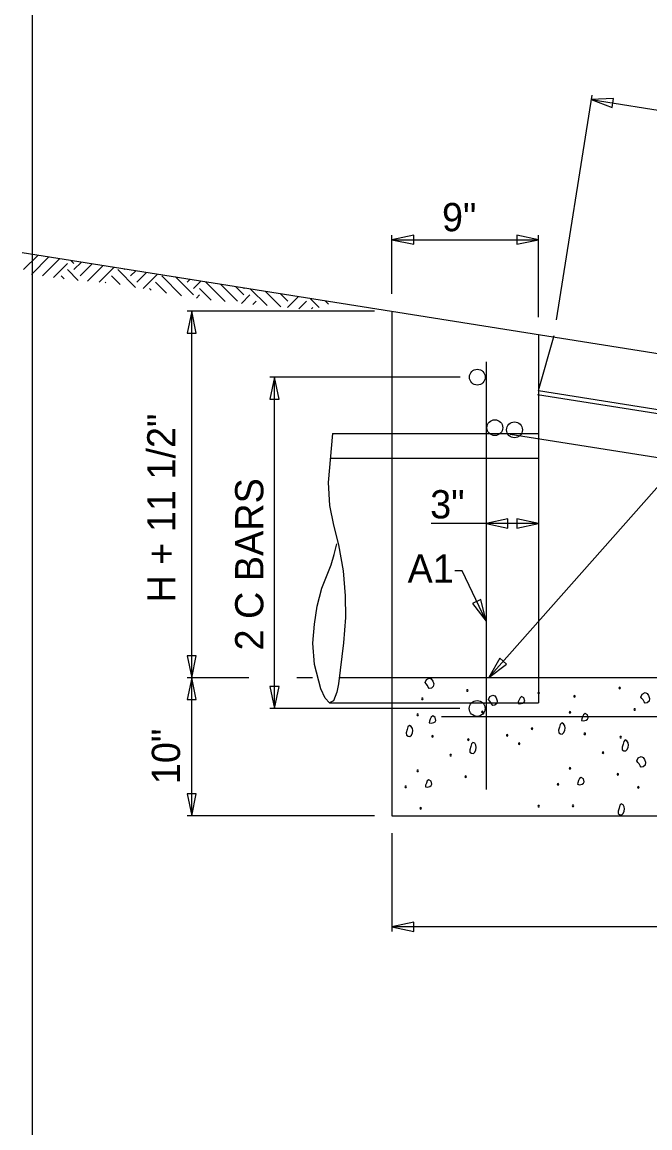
# Model space of a CAD drawing. Extents: x -439.2 to -407.9, y -458.1 to -436.2.
# Drawn here: x -439.16 to -435.83, y -452.18 to -446.32 of the extents above; entities that cross this region are included whole.
import ezdxf

# ---------------------------------------------------------------- set-up
doc = ezdxf.new("R2010")
doc.units = 0
for name, color, linetype in [('Bridge-Named Boundary', 7, 'Continuous'), ('Level 4', 7, 'Continuous'), ('Level 45', 7, 'Continuous')]:
    doc.layers.add(name, color=color, linetype=linetype)

msp = doc.modelspace()

# ---------------------------------------------------------------- linework, layer by layer
at = {"layer": 'Bridge-Named Boundary'}
msp.add_lwpolyline([(-439.109, -458.0508), (-407.859, -458.0508), (-407.859, -437.6758), (-439.109, -437.6758)], close=True, dxfattribs=at)
at = {"layer": 'Level 4'}
for p, q in [((-436.3245, -447.8963), (-436.1357, -446.7046)), ((-436.1395, -446.7284), (-430.9827, -447.5452)), ((-437.1989, -447.759), (-437.1989, -447.4476)), ((-436.4192, -447.8825), (-436.4192, -447.4476)), ((-437.1989, -447.4717), (-436.4192, -447.4717)), ((-439.1627, -447.54), (-425.6904, -449.6734)), ((-439.1551, -447.6305), (-439.0782, -447.5535)), ((-439.1136, -447.6558), (-439.0205, -447.5627)), ((-439.0549, -447.664), (-438.9628, -447.5718)), ((-438.8879, -447.5971), (-438.9038, -447.5812)), ((-438.9963, -447.6721), (-438.9213, -447.5971)), ((-438.8645, -447.6873), (-438.9213, -447.6305)), ((-438.8879, -447.6305), (-438.8475, -447.5901)), ((-438.8544, -447.6639), (-438.7898, -447.5993)), ((-438.8153, -447.6916), (-438.7321, -447.6084)), ((-438.7538, -447.697), (-438.6745, -447.6176)), ((-438.5601, -447.7244), (-438.654, -447.6305)), ((-438.6206, -447.6305), (-438.6168, -447.6267)), ((-438.5872, -447.6639), (-438.5591, -447.6359)), ((-438.9386, -447.68), (-438.9547, -447.6639)), ((-438.7177, -447.7005), (-438.7208, -447.6973)), ((-438.6419, -447.7095), (-438.6874, -447.6639)), ((-438.5537, -447.6973), (-438.5014, -447.645)), ((-438.5203, -447.7308), (-438.4438, -447.6542)), ((-438.3956, -447.7553), (-438.4535, -447.6973)), ((-438.3153, -447.7688), (-438.4201, -447.6639)), ((-438.2531, -447.7642), (-438.3478, -447.6694)), ((-438.2865, -447.6973), (-438.2708, -447.6816)), ((-438.2531, -447.7308), (-438.2131, -447.6908)), ((-438.0835, -447.8), (-438.1862, -447.6973)), ((-438.4779, -447.7398), (-438.4869, -447.7308)), ((-438.1583, -447.7921), (-438.2196, -447.7308)), ((-438.0192, -447.7976), (-438.1095, -447.7072)), ((-437.9858, -447.7642), (-438.0301, -447.7198)), ((-437.9858, -447.7308), (-437.9824, -447.7274)), ((-437.8619, -447.8212), (-437.9507, -447.7324)), ((-437.789, -447.8273), (-437.8713, -447.745)), ((-438.2372, -447.7818), (-438.2196, -447.7642)), ((-437.9974, -447.8092), (-437.9524, -447.7642)), ((-437.9364, -447.815), (-437.9189, -447.7976)), ((-437.7519, -447.7976), (-437.7918, -447.7576)), ((-437.7526, -447.8317), (-437.694, -447.7731)), ((-437.6931, -447.839), (-437.6517, -447.7976)), ((-437.5847, -447.8311), (-437.633, -447.7828)), ((-437.5352, -447.8138), (-437.5536, -447.7954)), ((-437.2907, -447.8509), (-438.2861, -447.8509)), ((-438.262, -450.5286), (-438.262, -447.8509)), ((-437.6256, -447.8384), (-437.6182, -447.831)), ((-437.1984, -447.8506), (-437.1984, -450.5281)), ((-436.6846, -449.7952), (-434.9984, -447.8922)), ((-436.4193, -447.9745), (-436.4193, -449.9295)), ((-436.4193, -448.2716), (-436.3374, -447.9797)), ((-436.6986, -448.1194), (-436.6986, -450.3884)), ((-436.8369, -448.2012), (-437.8461, -448.2012)), ((-437.822, -449.9585), (-437.822, -448.2012)), ((-436.4193, -448.2716), (-431.2564, -449.0896)), ((-436.4245, -448.2926), (-431.261, -449.11)), ((-437.5136, -448.4995), (-436.4193, -448.4995)), ((-436.5705, -448.5037), (-430.4973, -449.4655)), ((-436.4193, -448.6328), (-437.5256, -448.6328)), ((-436.4192, -448.9772), (-436.9909, -448.9772)), ((-436.825, -449.2287), (-436.8649, -449.2287)), ((-436.6985, -449.4959), (-436.825, -449.2287)), ((-437.9591, -449.7955), (-438.2861, -449.7955)), ((-437.6207, -449.7955), (-437.7027, -449.7955)), ((-437.4775, -449.7952), (-436.4193, -449.7952)), ((-436.4193, -449.7952), (-425.6904, -449.7952)), ((-436.8377, -449.9585), (-437.8461, -449.9585)), ((-437.5304, -449.9295), (-436.4193, -449.9295)), ((-436.9348, -450.001), (-431.0317, -450.001)), ((-437.2907, -450.5286), (-438.2861, -450.5286)), ((-437.1984, -450.5281), (-425.6904, -450.5281)), ((-437.1989, -450.6204), (-437.1989, -451.1415)), ((-425.6902, -451.1174), (-437.1989, -451.1174))]:
    msp.add_line(p, q, dxfattribs=at)
for points in [[(-436.021, -446.7228), (-436.1395, -446.7284), (-436.0285, -446.7704)], [(-437.0827, -447.4476), (-437.1989, -447.4717), (-437.0827, -447.4958)], [(-436.5354, -447.4958), (-436.4192, -447.4717), (-436.5354, -447.4476)], [(-438.2379, -447.967), (-438.262, -447.8509), (-438.2861, -447.967)], [(-437.7979, -448.3174), (-437.822, -448.2012), (-437.8461, -448.3174)], [(-436.5823, -448.9531), (-436.6985, -448.9772), (-436.5823, -449.0013)], [(-436.5354, -449.0013), (-436.4192, -448.9772), (-436.5354, -448.9531)], [(-436.77, -449.4012), (-436.6985, -449.4959), (-436.7264, -449.3806)], [(-438.2861, -449.6793), (-438.262, -449.7955), (-438.2379, -449.6793)], [(-436.6256, -449.6922), (-436.6846, -449.7952), (-436.5895, -449.7242)], [(-438.2379, -449.9116), (-438.262, -449.7955), (-438.2861, -449.9116)], [(-437.0219, -449.8208), (-437.0153, -449.8051), (-436.9998, -449.7975), (-436.9895, -449.8023), (-436.9816, -449.813), (-436.9759, -449.8283), (-436.979, -449.8429), (-436.9891, -449.8517), (-436.9998, -449.8533), (-437.0053, -449.8462), (-437.0102, -449.8364), (-437.0172, -449.8288), (-437.0219, -449.8208)], [(-437.8461, -449.8423), (-437.822, -449.9585), (-437.7979, -449.8423)], [(-436.6848, -449.9108), (-436.6783, -449.8951), (-436.6628, -449.8875), (-436.6525, -449.8923), (-436.6446, -449.9031), (-436.6389, -449.9183), (-436.642, -449.9329), (-436.652, -449.9417), (-436.6628, -449.9433), (-436.6682, -449.9362), (-436.6732, -449.9264), (-436.6802, -449.9188), (-436.6848, -449.9108)], [(-436.5098, -449.8957), (-436.5176, -449.9016), (-436.5228, -449.9126), (-436.5275, -449.9238), (-436.528, -449.932), (-436.5185, -449.9344), (-436.5046, -449.9307), (-436.4968, -449.926), (-436.4929, -449.9191), (-436.4972, -449.9031), (-436.5098, -449.8957)], [(-435.8759, -449.8979), (-435.8694, -449.8822), (-435.8539, -449.8746), (-435.8436, -449.8794), (-435.8357, -449.8902), (-435.83, -449.9054), (-435.8331, -449.92), (-435.8431, -449.9288), (-435.8539, -449.9304), (-435.8593, -449.9233), (-435.8642, -449.9135), (-435.8713, -449.9059), (-435.8759, -449.8979)], [(-436.1727, -449.9857), (-436.1805, -449.9916), (-436.1857, -450.0026), (-436.1905, -450.0138), (-436.1909, -450.022), (-436.1814, -450.0244), (-436.1676, -450.0207), (-436.1598, -450.016), (-436.1559, -450.0091), (-436.1601, -449.9931), (-436.1727, -449.9857)], [(-436.9817, -449.9986), (-436.9894, -450.0045), (-436.9946, -450.0155), (-436.9994, -450.0267), (-436.9998, -450.0349), (-436.9903, -450.0373), (-436.9765, -450.0337), (-436.9687, -450.0289), (-436.9648, -450.022), (-436.969, -450.006), (-436.9817, -449.9986)], [(-436.2966, -450.0358), (-436.3045, -450.0432), (-436.3083, -450.0579), (-436.3136, -450.0746), (-436.3121, -450.0877), (-436.304, -450.0933), (-436.294, -450.0942), (-436.2855, -450.0868), (-436.281, -450.0747), (-436.2792, -450.063), (-436.281, -450.0514), (-436.287, -450.0406), (-436.2966, -450.0358)], [(-437.1055, -450.0487), (-437.1134, -450.0561), (-437.1172, -450.0708), (-437.1225, -450.0876), (-437.1211, -450.1006), (-437.1129, -450.1062), (-437.1029, -450.1071), (-437.0945, -450.0997), (-437.0899, -450.0876), (-437.0881, -450.0759), (-437.0899, -450.0643), (-437.0959, -450.0535), (-437.1055, -450.0487)], [(-436.7684, -450.1387), (-436.7764, -450.1461), (-436.7801, -450.1608), (-436.7854, -450.1776), (-436.784, -450.1906), (-436.7758, -450.1962), (-436.7659, -450.1971), (-436.7574, -450.1897), (-436.7529, -450.1777), (-436.751, -450.1659), (-436.7529, -450.1543), (-436.7589, -450.1435), (-436.7684, -450.1387)], [(-435.9595, -450.1258), (-435.9675, -450.1332), (-435.9712, -450.1479), (-435.9765, -450.1646), (-435.9751, -450.1777), (-435.9669, -450.1833), (-435.9569, -450.1842), (-435.9485, -450.1768), (-435.944, -450.1647), (-435.9421, -450.153), (-435.944, -450.1414), (-435.95, -450.1306), (-435.9595, -450.1258)], [(-435.897, -450.2369), (-435.8904, -450.2212), (-435.8749, -450.2135), (-435.8646, -450.2184), (-435.8568, -450.2291), (-435.851, -450.2444), (-435.8542, -450.259), (-435.8642, -450.2678), (-435.8749, -450.2693), (-435.8804, -450.2623), (-435.8853, -450.2525), (-435.8923, -450.2449), (-435.897, -450.2369)], [(-437.0027, -450.3376), (-437.0105, -450.3435), (-437.0157, -450.3544), (-437.0205, -450.3657), (-437.0209, -450.3739), (-437.0114, -450.3762), (-436.9975, -450.3726), (-436.9898, -450.3678), (-436.9858, -450.3609), (-436.9901, -450.345), (-437.0027, -450.3376)], [(-436.1938, -450.3246), (-436.2016, -450.3305), (-436.2068, -450.3415), (-436.2115, -450.3528), (-436.212, -450.361), (-436.2025, -450.3633), (-436.1886, -450.3597), (-436.1808, -450.3549), (-436.1769, -450.348), (-436.1812, -450.3321), (-436.1938, -450.3246)], [(-438.2861, -450.4124), (-438.262, -450.5286), (-438.2379, -450.4124)], [(-435.9806, -450.4648), (-435.9885, -450.4722), (-435.9923, -450.4868), (-435.9976, -450.5036), (-435.9962, -450.5167), (-435.988, -450.5223), (-435.978, -450.5232), (-435.9696, -450.5158), (-435.965, -450.5037), (-435.9632, -450.492), (-435.965, -450.4803), (-435.971, -450.4695), (-435.9806, -450.4648)], [(-437.0827, -451.0933), (-437.1989, -451.1174), (-437.0827, -451.1415)]]:
    msp.add_lwpolyline(points, close=True, dxfattribs=at)
msp.add_lwpolyline([(-437.5136, -448.4995), (-437.537, -448.7596), (-437.5304, -448.8815), (-437.5083, -448.9856), (-437.4816, -449.0902), (-437.4573, -449.2278), (-437.446, -449.3611), (-437.4459, -449.4755), (-437.4549, -449.6098), (-437.4814, -449.8273), (-437.4912, -449.8718), (-437.5089, -449.918), (-437.5304, -449.9295), (-437.5526, -449.9049), (-437.5752, -449.8553), (-437.6103, -449.7253), (-437.6192, -449.613), (-437.6103, -449.5121), (-437.5953, -449.4166), (-437.5704, -449.3212), (-437.5461, -449.2588), (-437.5215, -449.1968), (-437.5044, -449.1418), (-437.4905, -449.0858)], dxfattribs=at)
for centre in [(-436.745, -448.2012), (-436.6519, -448.4689), (-436.5472, -448.4805), (-436.7458, -449.9585)]:
    msp.add_circle(centre, 0.042, dxfattribs=at)
for centre, start, end in [((-436.7976, -449.8632), 0, 180), ((-436.7976, -449.8632), 180, 0), ((-435.9887, -449.8503), 0, 180), ((-435.9887, -449.8503), 180, 0), ((-437.0375, -449.9077), 0, 180), ((-437.0375, -449.9077), 180, 0), ((-436.4193, -449.8772), 0, 180), ((-436.4193, -449.8772), 180, 0), ((-436.2286, -449.8948), 0, 180), ((-436.2286, -449.8948), 180, 0), ((-436.7186, -449.9772), 0, 180), ((-436.7186, -449.9772), 180, 0), ((-436.2531, -449.9793), 0, 180), ((-436.2531, -449.9793), 180, 0), ((-435.9097, -449.9643), 0, 180), ((-435.9097, -449.9643), 180, 0), ((-437.0621, -449.9922), 0, 180), ((-437.0621, -449.9922), 180, 0), ((-436.9831, -450.1062), 0, 180), ((-436.5863, -450.1018), 0, 180), ((-436.5863, -450.1018), 180, 0), ((-436.4543, -450.0657), 0, 180), ((-436.4543, -450.0657), 180, 0), ((-436.1742, -450.0933), 0, 180), ((-436.1742, -450.0933), 180, 0), ((-436.9831, -450.1062), 180, 0), ((-436.7923, -450.1237), 0, 180), ((-436.7923, -450.1237), 180, 0), ((-436.5225, -450.1454), 0, 180), ((-436.5225, -450.1454), 180, 0), ((-435.9834, -450.1108), 0, 180), ((-435.9834, -450.1108), 180, 0), ((-436.8863, -450.2067), 0, 180), ((-436.8863, -450.2067), 180, 0), ((-436.0774, -450.1937), 0, 180), ((-436.0774, -450.1937), 180, 0), ((-436.2527, -450.2769), 0, 180), ((-436.2527, -450.2769), 180, 0), ((-437.0617, -450.2898), 0, 180), ((-437.0617, -450.2898), 180, 0), ((-436.8073, -450.3207), 0, 180), ((-436.8073, -450.3207), 180, 0), ((-435.9984, -450.3078), 0, 180), ((-435.9984, -450.3078), 180, 0), ((-437.125, -450.3744), 0, 180), ((-437.125, -450.3744), 180, 0), ((-436.316, -450.3615), 0, 180), ((-436.316, -450.3615), 180, 0), ((-435.8903, -450.3776), 0, 180), ((-435.8903, -450.3776), 180, 0), ((-437.046, -450.4884), 0, 180), ((-437.046, -450.4884), 180, 0), ((-436.4188, -450.4769), 0, 180), ((-436.4188, -450.4769), 180, 0), ((-436.2371, -450.4755), 0, 180), ((-436.2371, -450.4755), 180, 0)]:
    msp.add_arc(centre, 0.00416, start, end, dxfattribs=at)

# ---------------------------------------------------------------- texts
msp.add_text('2 C BARS', height=0.15, rotation=90, dxfattribs=at).set_placement((-437.8813, -449.6511))
msp.add_text('A1', height=0.15, dxfattribs=at).set_placement((-437.1153, -449.2917))
at = {"layer": 'Level 45'}
for s, p in [('9"', (-436.9325, -447.4267)), ('3"', (-436.9953, -448.9504))]:
    msp.add_text(s, height=0.15, dxfattribs=at).set_placement(p)
for s, p in [('H + 11 1/2"', (-438.3483, -449.3966)), ('10"', (-438.3239, -450.3604))]:
    msp.add_text(s, height=0.15, rotation=90, dxfattribs=at).set_placement(p)

doc.saveas('drawing.dxf')
